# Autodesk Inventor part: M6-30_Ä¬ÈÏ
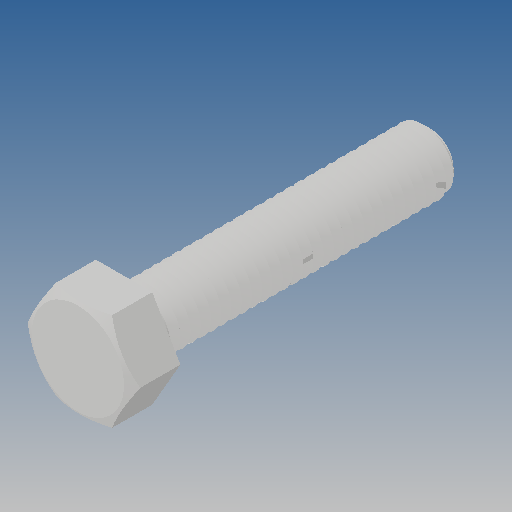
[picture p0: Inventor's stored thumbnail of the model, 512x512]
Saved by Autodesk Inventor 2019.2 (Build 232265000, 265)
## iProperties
Created: 2010-06
Part Number: M6-30_Ä¬ÈÏ
Material: Ogólny
Document SubType Name: Modeling
Designer: CADENGINEERING4
Density: 1 g/cm^3
Appearance: Domyślna
Author: CADENGINEERING4
Revision Number: ÈÎºÎ
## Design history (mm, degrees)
feature "NONE"
node "Bryła1"
